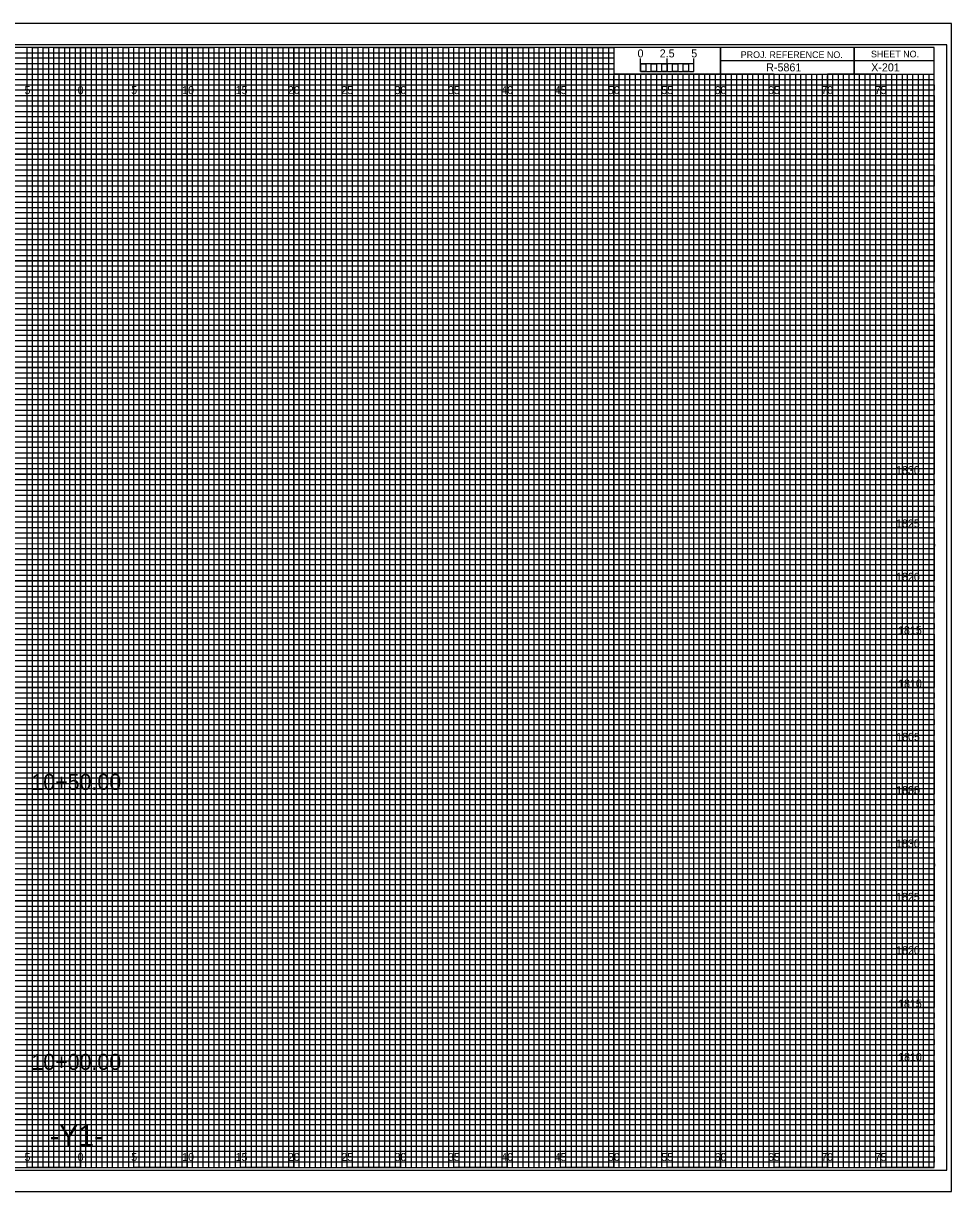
# Model space of a CAD drawing. Extents: x -7 to 162, y -2 to 767.
# Drawn here: x 74.6 to 161.7, y -2.3 to 107.3 of the extents above; entities that cross this region are included whole.
import ezdxf

# ---------------------------------------------------------------- set-up
doc = ezdxf.new("R2010")
doc.units = 0
for name, color, linetype in [('Prop Grid Mask', 7, 'Continuous'), ('Prop XS Alignment Label', 7, 'Continuous'), ('Prop XS Bar Scale Labels', 7, 'Continuous'), ('Prop XS Elevation Labels', 7, 'Continuous'), ('Prop XS Project Number', 7, 'Continuous'), ('Prop XS Sheet Number', 7, 'Continuous'), ('Prop XS Station Labels', 7, 'Continuous'), ('Sheet Cross Section CELL', 7, 'Continuous'), ('Sheet Cross Section Grid Major CELL', 7, 'Continuous'), ('Sheet Cross Section Grid Middle CELL', 7, 'Continuous'), ('Sheet Cross Section Grid Minor 1 CELL', 7, 'Continuous'), ('Sheet Cross Section Grid Minor 2 CELL', 7, 'Continuous'), ('Sheet Cross Section Scale CELL', 7, 'Continuous'), ('Sheet Cutting Line CELL', 7, 'Continuous'), ('Sheet DOT Grid CELL', 7, 'Continuous'), ('Sheet Plot Border Inside CELL', 7, 'Continuous'), ('Sheet Plot Border Outside CELL', 7, 'Continuous')]:
    doc.layers.add(name, color=color, linetype=linetype)

msp = doc.modelspace()

# ---------------------------------------------------------------- linework, layer by layer
at = {"layer": 'Sheet Cross Section CELL'}
for p, q in [((152.5, 105), (152.5, 102.5)), ((152.5, 102.5), (152.5, 105)), ((160, 103.75), (140, 103.75)), ((140, 103.75), (140, 102.5)), ((140, 102.5), (160, 102.5))]:
    msp.add_line(p, q, dxfattribs=at)
for points in [[(160, 105), (0, 105), (0, 0), (160, 0)], [(140, 105), (130, 105), (130, 102.52), (140, 102.52)], [(160, 105), (140, 105), (140, 102.5), (160, 102.5)]]:
    msp.add_lwpolyline(points, close=True, dxfattribs=at)
at = {"layer": 'Sheet Cross Section Grid Major CELL'}
for p, q in [((75, 105), (70, 105)), ((75, 0), (75, 105)), ((85, 105), (80, 105)), ((80, 105), (80, 0)), ((85, 0), (85, 105)), ((95, 105), (90, 105)), ((90, 105), (90, 0)), ((95, 0), (95, 105)), ((105, 105), (100, 105)), ((100, 105), (100, 0)), ((105, 0), (105, 105)), ((115, 105), (110, 105)), ((110, 105), (110, 0)), ((115, 0), (115, 105)), ((125, 105), (120, 105)), ((120, 105), (120, 0)), ((125, 0), (125, 105)), ((130, 105), (130, 0)), ((135, 0), (135, 102.5)), ((145, 102.5), (140, 102.5)), ((140, 102.5), (140, 0)), ((145, 0), (145, 102.5)), ((155, 102.5), (150, 102.5)), ((150, 102.5), (150, 0)), ((155, 0), (155, 102.5)), ((80, 0), (75, 0)), ((90, 0), (85, 0)), ((100, 0), (95, 0)), ((110, 0), (105, 0)), ((120, 0), (115, 0)), ((130, 0), (125, 0)), ((140, 0), (135, 0)), ((150, 0), (145, 0)), ((160, 0), (155, 0)), ((160, 0), (160, 0))]:
    msp.add_line(p, q, dxfattribs=at)
for points in [[(0, 100), (160, 100), (160, 95), (0, 95)], [(0, 90), (160, 90), (160, 85), (0, 85)], [(0, 80), (160, 80), (160, 75), (0, 75)], [(0, 70), (160, 70), (160, 65), (0, 65)], [(0, 60), (160, 60), (160, 55), (0, 55)], [(0, 50), (160, 50), (160, 45), (0, 45)], [(0, 40), (160, 40), (160, 35), (0, 35)], [(0, 30), (160, 30), (160, 25), (0, 25)], [(0, 20), (160, 20), (160, 15), (0, 15)], [(0, 10), (160, 10), (160, 5), (0, 5)]]:
    msp.add_lwpolyline(points, dxfattribs=at)
at = {"layer": 'Sheet Cross Section Grid Middle CELL'}
for points in [[(72.5, 0), (77.5, 0), (77.5, 105), (82.5, 105), (82.5, 0), (87.5, 0), (87.5, 105), (92.5, 105), (92.5, 0), (97.5, 0), (97.5, 105), (102.5, 105), (102.5, 0), (107.5, 0), (107.5, 105), (112.5, 105), (112.5, 0), (117.5, 0), (117.5, 105), (122.5, 105), (122.5, 0), (127.5, 0), (127.5, 105), (129.97, 105), (130, 105), (130, 102.5), (132.5, 102.5), (132.5, 0), (137.5, 0), (137.5, 102.5), (142.5, 102.5), (142.5, 0), (147.5, 0), (147.5, 102.5), (152.5, 102.5), (152.5, 0), (157.5, 0), (157.5, 102.5)], [(0, 102.5), (137.5, 102.5)], [(0, 92.5), (160, 92.5), (160, 97.5), (0, 97.5)], [(0, 82.5), (160, 82.5), (160, 87.5), (0, 87.5)], [(0, 72.5), (160, 72.5), (160, 77.5), (0, 77.5)], [(0, 62.5), (160, 62.5), (160, 67.5), (0, 67.5)], [(0, 52.5), (160, 52.5), (160, 57.5), (0, 57.5)], [(0, 42.5), (160, 42.5), (160, 47.5), (0, 47.5)], [(0, 32.5), (160, 32.5), (160, 37.5), (0, 37.5)], [(0, 22.5), (160, 22.5), (160, 27.5), (0, 27.5)], [(0, 12.5), (160, 12.5), (160, 17.5), (0, 17.5)], [(0, 2.5), (160, 2.5), (160, 7.5), (0, 7.5)]]:
    msp.add_lwpolyline(points, dxfattribs=at)
at = {"layer": 'Sheet Cross Section Grid Minor 1 CELL'}
for p, q in [((0, 104.5), (130, 104.5)), ((130, 104.5), (130, 103.99)), ((130, 103.99), (0, 103.99)), ((0, 103.5), (130, 103.5)), ((130, 102.95), (0, 102.95)), ((130, 103.5), (130, 102.95)), ((0, 102), (160, 102))]:
    msp.add_line(p, q, dxfattribs=at)
for points in [[(0, 101.5), (135, 101.5), (160, 101.5), (160, 101), (0, 101)], [(0, 100.5), (160, 100.5), (160, 99.5), (0, 99.5)], [(0, 99), (160, 99), (160, 98.5), (0, 98.49)], [(0, 98), (160, 98), (160, 97), (0, 97)], [(0, 96.5), (160, 96.5), (160, 96), (0, 96)], [(0, 95.5), (160, 95.5), (160, 94.5), (0, 94.5)], [(0, 94), (160, 94), (160, 93.5), (0, 93.5)], [(0, 93), (160, 93), (160, 92), (0, 92)], [(0, 91.5), (160, 91.5), (160, 91), (0, 91)], [(0, 90.5), (160, 90.5), (160, 89.5), (0, 89.5)], [(0, 89), (160, 89), (160, 88.5), (0, 88.5)], [(0, 88), (160, 88), (160, 86.98), (160, 86.5), (160, 86), (0, 86)], [(0, 87), (160, 87), (160, 86.5), (0, 86.5)], [(0, 85.5), (160, 85.5), (160, 84.5), (0, 84.52)], [(0, 84.52), (160, 84.5), (160, 84), (0, 84)], [(0, 83.5), (160, 83.5), (160, 83), (0, 83)], [(0, 82), (160, 82), (160, 81.5), (0, 81.5)], [(0, 81), (160, 81), (160, 80.5), (0, 80.5)], [(-0.04, 79.45), (160, 79.45), (160, 78.94), (-0.04, 78.94)], [(0, 78.5), (160, 78.5), (160, 78), (0, 78)], [(0, 77), (160, 77), (160, 76.5), (0, 76.5)], [(0, 76), (160, 76), (160, 75.5), (0, 75.5)], [(0, 74.5), (160, 74.5), (160, 74), (0, 74)], [(0, 73.5), (160, 73.5), (160, 73), (0, 73)], [(0, 72), (160, 72), (160, 71.5), (0, 71.5)], [(0, 71), (160, 71), (160, 70.5), (0, 70.5)], [(0, 69.5), (160, 69.5), (160, 68.99), (0, 69)], [(0, 68.5), (160, 68.5), (160, 68), (0, 68)], [(0, 67), (160, 67), (160, 66.5), (0, 66.5)], [(0, 66), (160, 66), (160, 65.5), (0, 65.5)], [(0, 64.5), (160, 64.5), (160, 64), (0, 64)], [(0, 63.5), (160, 63.5), (160, 63), (0, 63)], [(0, 62), (160, 62), (160, 61.5), (0, 61.5)], [(0, 61), (160, 61), (160, 60.5), (0, 60.5)], [(0, 59.5), (160, 59.5), (160, 59), (0, 59)], [(0, 58.5), (160.03, 58.45), (160, 58), (0, 58)], [(0, 57), (160, 57), (160, 56.5), (0, 56.5)], [(0, 56), (160, 56), (160, 55.5), (0, 55.5)], [(0, 54.5), (160, 54.5), (160, 54), (0, 54)], [(0, 53.5), (160, 53.5), (160, 53), (0, 53)], [(0, 52), (160, 52), (160, 51.5), (0, 51.5)], [(0, 51), (160, 51), (160, 50.5), (0, 50.5)], [(0, 49.5), (160, 49.5), (160, 49), (0, 49)], [(0, 48.5), (160, 48.5), (160, 48), (0, 48)], [(0, 47), (160, 47), (160, 46.5), (0, 46.5)], [(0, 46), (160, 46), (160, 45.5), (0, 45.5)], [(0, 44.5), (160, 44.5), (160, 44), (0, 44)], [(0, 43.5), (160, 43.5), (160, 43), (0, 43)], [(0, 42), (160, 42), (160, 41.5), (0, 41.5)], [(0, 41), (160, 41), (160, 40.5), (0, 40.5)], [(0, 39.5), (160, 39.5), (160, 38.99), (0, 39)], [(0, 38.5), (160, 38.5), (160, 38), (0, 38)], [(0, 37), (160, 37), (160, 36.5), (0, 36.5)], [(0, 36), (160, 36), (160, 35.5), (0, 35.5)], [(0, 34.5), (160, 34.5), (160, 34), (0, 34)], [(0, 33.5), (160, 33.5), (160, 33), (0, 33)], [(0, 32), (160, 32), (160, 31.5), (0, 31.5)], [(0, 31), (160, 31), (160, 30.5), (0, 30.5)], [(0, 29.5), (160, 29.5), (160, 29), (0, 29)], [(0, 28.5), (160.03, 28.46), (160, 28), (0, 28)], [(0, 27), (160, 27), (160, 26.5), (0, 26.5)], [(0, 26), (160, 26), (160, 25.5), (0, 25.5)], [(0, 24.5), (160, 24.5), (160, 24), (0, 24)], [(0, 23.5), (160, 23.5), (160, 23), (0, 23)], [(0, 22), (160, 22), (160, 21.5), (0, 21.5)], [(0, 21), (160, 21), (160, 20.5), (0, 20.5)], [(0, 19.5), (160, 19.5), (160, 19), (0, 19)], [(0, 18.5), (160, 18.5), (160, 18), (0, 18)], [(0, 17), (160, 17), (160, 16.5), (0, 16.5)], [(0, 16), (160, 16), (160, 15.5), (0, 15.5)], [(0, 14.5), (160, 14.5), (160, 14), (0, 14)], [(0, 13.5), (160, 13.5), (160, 13), (0, 13)], [(0, 12), (160, 12), (160, 11.5), (0, 11.5)], [(0, 11), (160, 11), (160, 10.5), (0, 10.5)], [(0, 9.5), (160, 9.5), (160, 9), (0, 9)], [(0, 8.5), (160, 8.5), (160, 8), (0, 8)], [(0, 7), (160, 7), (160, 6.5), (0, 6.5)], [(0, 6), (160, 6), (160, 5.5), (0, 5.5)], [(0, 4.5), (160, 4.5), (160, 4), (0, 4)], [(0, 3.5), (160, 3.5), (160, 3), (0, 3)], [(0, 2), (160, 2), (160, 1.5), (0, 1.5)], [(0, 1), (160, 1), (160, 0.5), (0, 0.5)]]:
    msp.add_lwpolyline(points, dxfattribs=at)
at = {"layer": 'Sheet Cross Section Grid Minor 2 CELL'}
for p, q in [((133.5, 102.5), (133, 102.5)), ((133, 102.5), (133, 0)), ((133.5, 0), (133.5, 102.5)), ((134.5, 102.5), (134, 102.5)), ((134, 102.5), (134, 0)), ((134.5, 0), (134.5, 102.5)), ((133, 0), (132.5, 0)), ((134, 0), (133.5, 0))]:
    msp.add_line(p, q, dxfattribs=at)
for points in [[(75, 0), (75.5, 0), (75.5, 105), (76, 105), (76, 0)], [(76, 0), (76.5, 0), (76.5, 105), (77, 105), (77, 0)], [(77.5, 0), (78, 0), (78, 105), (78.5, 105), (78.5, 0)], [(78.5, 0), (79, 0), (79, 105), (79.5, 105), (79.5, 0)], [(80, 0), (80.5, 0), (80.5, 105), (81, 105), (81, 0)], [(81, 0), (81.5, 0), (81.5, 105), (82, 105), (82, 0)], [(82.5, 0), (83, 0), (83, 105), (83.5, 105), (83.5, 0)], [(83.5, 0), (84, 0), (84, 105), (84.5, 105), (84.5, 0)], [(85, 0), (85.5, 0), (85.5, 105), (86, 105), (86, 0)], [(86, 0), (86.5, 0), (86.5, 105), (87, 105), (87, 0)], [(87.5, 0), (88, 0), (88, 105), (88.5, 105), (88.5, 0)], [(88.5, 0), (89, 0), (89, 105), (89.5, 105), (89.5, 0)], [(90, 0), (90.5, 0), (90.5, 105), (91, 105), (91, 0)], [(91, 0), (91.5, 0), (91.5, 105), (92, 105), (92, 0)], [(92.5, 0), (93, 0), (93, 105), (93.5, 105), (93.5, 0)], [(93.5, 0), (94, 0), (94, 105), (94.5, 105), (94.5, 0)], [(95, 0), (95.5, 0), (95.5, 105), (96, 105), (96, 0)], [(96, 0), (96.5, 0), (96.5, 105), (97, 105), (97, 0)], [(97.5, 0), (98, 0), (98, 105), (98.5, 105), (98.5, 0)], [(98.5, 0), (99, 0), (99, 105), (99.5, 105), (99.5, 0)], [(100, 0), (100.5, 0), (100.5, 105), (101, 105), (101, 0)], [(101, 0), (101.5, 0), (101.5, 105), (102, 105), (102, 0)], [(102.5, 0), (103, 0), (103, 105), (103.5, 105), (103.5, 0)], [(103.5, 0), (104, 0), (104, 105), (104.5, 105), (104.5, 0)], [(105, 0), (105.5, 0), (105.5, 105), (106, 105), (106, 0)], [(106, 0), (106.5, 0), (106.5, 105), (107, 105), (107, 0)], [(107.5, 0), (108, 0), (108, 105), (108.5, 105), (108.5, 0)], [(108.5, 0), (109, 0), (109, 105), (109.5, 105), (109.5, 0)], [(110, 0), (110.5, 0), (110.5, 105), (111, 105), (111, 0)], [(111, 0), (111.5, 0), (111.5, 105), (112, 105), (112, 0)], [(112.5, 0), (113, 0), (113, 105), (113.5, 105), (113.5, 0)], [(113.5, 0), (114, 0), (114, 105), (114.5, 105), (114.5, 0)], [(115, 0), (115.5, 0), (115.5, 105), (116, 105), (116, 0)], [(116, 0), (116.5, 0), (116.5, 105), (117, 105), (117, 0)], [(117.5, 0), (118, 0), (118, 105), (118.5, 105), (118.5, 0)], [(118.5, 0), (119, 0), (119, 105), (119.5, 105), (119.5, 0)], [(120, 0), (120.5, 0), (120.5, 105), (121, 105), (121, 0)], [(121, 0), (121.5, 0), (121.5, 105), (122, 105), (122, 0)], [(122.5, 0), (123, 0), (123, 105), (123.5, 105), (123.5, 0)], [(123.5, 0), (124, 0), (124, 105), (124.5, 105), (124.5, 0)], [(125, 0), (125.5, 0), (125.5, 105), (126, 105), (126, 0)], [(126, 0), (126.5, 0), (126.5, 105), (127, 105), (127, 0)], [(127.5, 0), (128, 0), (128, 105), (128.5, 105), (128.5, 0)], [(128.5, 0), (129, 0), (129, 105), (129.5, 105), (129.5, 0)], [(130, 0), (130.5, 0), (130.5, 102.5), (131.01, 102.5), (131.01, 0)], [(131, 0), (131.5, 0), (131.5, 102.5), (132, 102.5), (132, 0)], [(135, 0), (135.49, 0), (135.49, 102.5), (136, 102.5), (136, 0)], [(136, 0), (136.5, 0), (136.5, 102.5), (137.03, 102.5), (137.03, 0)], [(137.5, 0), (138, 0), (138, 102.5), (138.5, 102.5), (138.5, 0)], [(138.5, 0), (139, 0), (139, 102.5), (139.5, 102.5), (139.5, 0)], [(140, 0), (140.5, 0), (140.5, 102.5), (141, 102.5), (141, 0)], [(141, 0), (141.5, 0), (141.5, 102.5), (142, 102.5), (142, 0)], [(142.5, 0), (143, 0), (143, 102.5), (143.5, 102.5), (143.5, 0)], [(143.5, 0), (144, 0), (144, 102.5), (144.5, 102.5), (144.5, 0)], [(145, 0), (145.5, 0), (145.5, 102.5), (146, 102.5), (146, 0)], [(146, 0), (146.5, 0), (146.5, 102.5), (147, 102.5), (147, 0)], [(147.5, 0), (148, 0), (148, 102.5), (148.5, 102.5), (148.5, 0)], [(148.5, 0), (149, 0), (149, 102.5), (149.5, 102.5), (149.5, 0)], [(150, 0), (150.5, 0), (150.5, 102.5), (151, 102.5), (151, 0)], [(151, 0), (151.5, 0), (151.5, 102.5), (152, 102.5), (152, 0)], [(152.5, 0), (153, 0), (153, 102.5), (153.5, 102.5), (153.5, 0)], [(153.5, 0), (154, 0), (154, 102.5), (154.5, 102.5), (154.5, 0)], [(155, 0), (155.5, 0), (155.5, 102.5), (156, 102.5), (156, 0)], [(156, 0), (156.5, 0), (156.5, 102.5), (157, 102.5), (157, 0)], [(157.5, 0), (158, 0), (158, 102.5), (158.5, 102.5), (158.5, 0)], [(158.5, 0), (159, 0), (159, 102.5), (159.5, 102.5), (159.5, 0)]]:
    msp.add_lwpolyline(points, dxfattribs=at)
at = {"layer": 'Sheet Cross Section Scale CELL'}
for p, q in [((132.5, 102.75), (132.5, 103.95)), ((132.5, 103.45), (132.5, 103.95)), ((135, 102.75), (135, 103.95)), ((137.5, 102.75), (137.5, 103.95)), ((137.5, 103.45), (137.5, 103.95))]:
    msp.add_line(p, q, dxfattribs=at)
for points in [[(137.5, 103.45), (132.5, 103.45), (132.5, 102.75), (137.5, 102.75)], [(132.5, 103.45), (133, 103.45), (133, 102.75), (132.5, 102.75)], [(133.5, 103.45), (134, 103.45), (134, 102.75), (133.5, 102.75)], [(134.5, 103.45), (135, 103.45), (135, 102.75), (134.5, 102.75)], [(135.5, 103.45), (136, 103.45), (136, 102.75), (135.5, 102.75)], [(136.5, 103.45), (137, 103.45), (137, 102.75), (136.5, 102.75)]]:
    msp.add_lwpolyline(points, close=True, dxfattribs=at)
at = {"layer": 'Sheet Cutting Line CELL'}
for p, q in [((161.65, 107.25), (-6.7, 107.25)), ((-6.7, -2.25), (161.65, -2.25))]:
    msp.add_line(p, q, dxfattribs=at)
at = {"layer": 'Sheet DOT Grid CELL'}
for p, q in [((75, 0), (75, 105)), ((80, 0), (80, 105)), ((85, 0), (85, 105)), ((90, 0), (90, 105)), ((95, 0), (95, 105)), ((100, 0), (100, 105)), ((105, 0), (105, 105)), ((110, 0), (110, 105)), ((115, 0), (115, 105)), ((120, 0), (120, 105)), ((125, 0), (125, 105)), ((130, 0), (130, 102.34)), ((135, 0), (135, 102.34)), ((140, 0), (140, 102.34)), ((145, 0), (145, 102.34)), ((150, 0), (150, 102.34)), ((155, 0), (155, 102.34)), ((0, 100), (160, 100)), ((0, 95), (160, 95)), ((0, 90), (160, 90)), ((0, 85), (160, 85)), ((0, 80), (160, 80)), ((0, 75), (160, 75)), ((0, 70), (160, 70)), ((0, 65), (160, 65)), ((0, 60), (160, 60)), ((0, 55), (160, 55)), ((0, 50), (160, 50)), ((0, 45), (160, 45)), ((0, 40), (160, 40)), ((0, 35), (160, 35)), ((0, 30), (160, 30)), ((0, 25), (160, 25)), ((0, 20), (160, 20)), ((0, 15), (160, 15)), ((0, 10), (160, 10)), ((0, 5), (160, 5))]:
    msp.add_line(p, q, dxfattribs=at)
at = {"layer": 'Sheet Plot Border Inside CELL'}
msp.add_lwpolyline([(-5.4, -0.25), (161.2, -0.25), (161.2, 105.25), (-5.4, 105.25)], close=True, dxfattribs=at)
at = {"layer": 'Sheet Plot Border Outside CELL'}
msp.add_lwpolyline([(-6.7, -2.25), (161.65, -2.25), (161.65, 107.25), (-6.7, 107.25)], close=True, dxfattribs=at)

# ---------------------------------------------------------------- texts
at = {"layer": 'Prop Grid Mask'}
for s, p in [('5', (74.74, 100.62)), ('0', (79.73, 100.62)), ('0', (79.73, 100.62)), ('5', (84.74, 100.62)), ('10', (89.52, 100.62)), ('15', (94.53, 100.62)), ('20', (99.43, 100.62)), ('25', (104.44, 100.62)), ('30', (109.43, 100.62)), ('35', (114.44, 100.62)), ('40', (119.43, 100.62)), ('45', (124.44, 100.62)), ('50', (129.43, 100.62)), ('55', (134.44, 100.62)), ('60', (139.43, 100.62)), ('65', (144.44, 100.62)), ('70', (149.43, 100.62)), ('75', (154.44, 100.62)), ('5', (74.74, 0.62)), ('0', (79.73, 0.62)), ('0', (79.73, 0.62)), ('5', (84.74, 0.62)), ('10', (89.52, 0.62)), ('15', (94.53, 0.62)), ('20', (99.43, 0.62)), ('25', (104.44, 0.62)), ('30', (109.43, 0.62)), ('35', (114.44, 0.62)), ('40', (119.43, 0.62)), ('45', (124.44, 0.62)), ('50', (129.43, 0.62)), ('55', (134.44, 0.62)), ('60', (139.43, 0.62)), ('65', (144.44, 0.62)), ('70', (149.43, 0.62)), ('75', (154.44, 0.62))]:
    msp.add_text(s, height=0.75, dxfattribs=at).set_placement(p)
at = {"layer": 'Prop XS Alignment Label'}
msp.add_text('-Y1-', height=2, dxfattribs=at).set_placement((77.11, 2))
at = {"layer": 'Prop XS Bar Scale Labels'}
for s, p in [('2.5', (134.29, 104.06)), ('5', (137.24, 104.06))]:
    msp.add_text(s, height=0.75, dxfattribs=at).set_placement(p)
at = {"layer": 'Prop XS Elevation Labels'}
for s, p in [('1830', (156.43, 65)), ('1825', (156.43, 60)), ('1820', (156.44, 55)), ('1815', (156.62, 50)), ('1810', (156.63, 45)), ('1805', (156.45, 40)), ('1835', (156.42, 35)), ('1800', (156.46, 35)), ('1830', (156.43, 30)), ('1825', (156.43, 25)), ('1820', (156.44, 20)), ('1815', (156.62, 15)), ('1810', (156.63, 10))]:
    msp.add_text(s, height=0.75, dxfattribs=at).set_placement(p)
at = {"layer": 'Prop XS Project Number'}
msp.add_text('R-5861', height=0.75, dxfattribs=at).set_placement((144.27, 102.75))
at = {"layer": 'Prop XS Sheet Number'}
msp.add_text('X-201', height=0.75, dxfattribs=at).set_placement((154.11, 102.75))
at = {"layer": 'Prop XS Station Labels'}
for s, p in [('10+50.00', (75.39, 35.4)), ('10+00.00', (75.39, 9.16))]:
    msp.add_text(s, height=1.5, dxfattribs=at).set_placement(p)
at = {"layer": 'Sheet Cross Section CELL'}
for s, p in [('PROJ. REFERENCE NO.', (141.88, 104)), ('SHEET NO.', (154.09, 104.06))]:
    msp.add_text(s, height=0.625, dxfattribs=at).set_placement(p)
at = {"layer": 'Sheet Cross Section Scale CELL'}
msp.add_text('0', height=0.75, dxfattribs=at).set_placement((132.21, 104.06))

doc.saveas('drawing.dxf')
